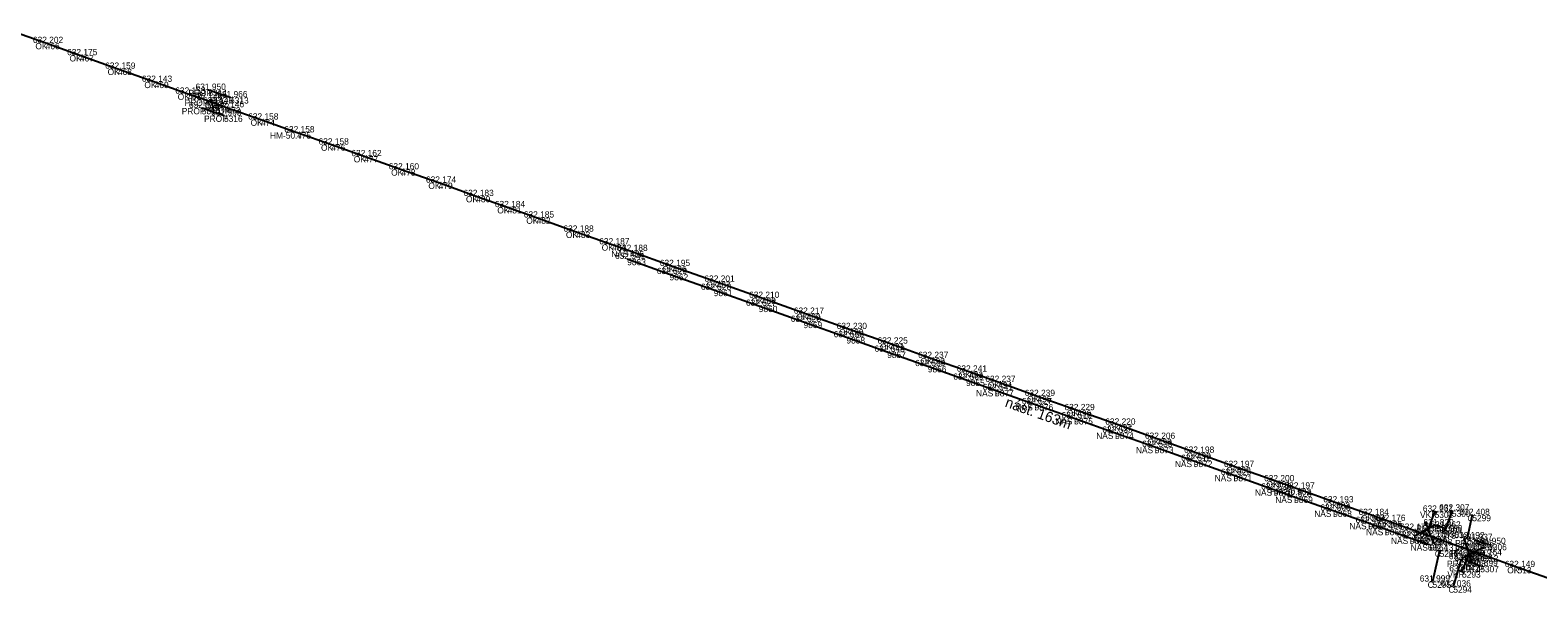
# Model space of a CAD drawing. Extents: x -631472 to -620808, y -1122356 to -1115125.
# Drawn here: x -628808.2 to -628519.1, y -1116376 to -1116268.1 of the extents above; entities that cross this region are included whole.
import ezdxf

# ---------------------------------------------------------------- set-up
doc = ezdxf.new("R2010")
doc.units = 0
for name, color, linetype in [('Vrstva 1', 7, 'Continuous'), ('Vrstva 14', 7, 'Continuous'), ('Vrstva 18', 7, 'Continuous'), ('Vrstva 4', 7, 'Continuous'), ('Vrstva 51', 7, 'Continuous'), ('Vrstva 60', 7, 'Continuous'), ('Vrstva 61', 7, 'Continuous'), ('Vrstva 62', 7, 'Continuous')]:
    doc.layers.add(name, color=color, linetype=linetype)

msp = doc.modelspace()

# ---------------------------------------------------------------- linework, layer by layer
at = {"layer": 'Vrstva 1'}
msp.add_lwpolyline([(-628812.06, -1116268.09), (-628805.17, -1116270.55), (-628798.61, -1116272.89), (-628791.32, -1116275.49), (-628784.27, -1116278), (-628777.88, -1116280.27), (-628774.68, -1116281.4), (-628772.66, -1116282.12), (-628770.48, -1116282.89), (-628763.9, -1116285.23), (-628756.97, -1116287.69), (-628750.4, -1116290.02), (-628744.11, -1116292.25), (-628736.94, -1116294.79), (-628729.81, -1116297.33), (-628722.61, -1116299.9), (-628716.6, -1116302.03), (-628711.03, -1116304.02), (-628703.43, -1116306.73), (-628696.58, -1116309.17), (-628693.1, -1116310.42), (-628684.96, -1116313.32), (-628676.51, -1116316.33), (-628667.85, -1116319.42), (-628659.27, -1116322.47), (-628651.05, -1116325.4), (-628643.21, -1116328.19), (-628635.44, -1116330.95), (-628628.12, -1116333.56), (-628622.55, -1116335.55), (-628614.99, -1116338.24), (-628607.38, -1116340.95), (-628599.55, -1116343.73), (-628591.93, -1116346.45), (-628584.44, -1116349.12), (-628576.8, -1116351.85), (-628569.1, -1116354.59), (-628565.19, -1116355.99), (-628557.75, -1116358.64), (-628550.97, -1116361.05), (-628547.78, -1116362.19), (-628543.02, -1116363.89), (-628539.28, -1116365.22), (-628538.12, -1116365.64), (-628532.43, -1116367.66), (-628531.94, -1116367.83), (-628530.62, -1116368.3), (-628529.3, -1116368.78), (-628522.94, -1116371.04), (-628516.08, -1116373.48)], dxfattribs=at)
at = {"layer": 'Vrstva 14'}
msp.add_lwpolyline([(-628693.66, -1116311.96), (-628685.54, -1116314.86), (-628677.07, -1116317.89), (-628668.44, -1116320.95), (-628659.85, -1116324.02), (-628651.63, -1116326.97), (-628643.8, -1116329.76), (-628636.01, -1116332.51), (-628628.69, -1116335.12), (-628623.13, -1116337.11), (-628615.55, -1116339.8), (-628607.94, -1116342.49), (-628600.1, -1116345.27), (-628592.48, -1116348), (-628585.02, -1116350.67), (-628577.38, -1116353.39), (-628569.66, -1116356.17), (-628565.77, -1116357.54), (-628558.29, -1116360.21), (-628551.55, -1116362.58), (-628548.35, -1116363.73), (-628543.57, -1116365.41), (-628539.81, -1116366.7)], dxfattribs=at)
at = {"layer": 'Vrstva 18'}
for p, q in [((-628773.98, -1116279.53), (-628769.82, -1116280.96)), ((-628775.25, -1116283.01), (-628770.98, -1116284.47)), ((-628538.54, -1116363.03), (-628537.2, -1116363.46)), ((-628531.09, -1116365.85), (-628528.58, -1116366.62)), ((-628532.63, -1116369.8), (-628530.09, -1116370.83))]:
    msp.add_line(p, q, dxfattribs=at)
at = {"layer": 'Vrstva 4'}
for p, q in [((-628538.38, -1116360.59), (-628539.32, -1116360.24)), ((-628538.74, -1116362.97), (-628542.77, -1116365.19)), ((-628539.03, -1116366.6), (-628540.61, -1116362.27)), ((-628538.85, -1116360.42), (-628540.08, -1116363.7)), ((-628538.12, -1116365.64), (-628532.43, -1116367.66)), ((-628533.17, -1116365.7), (-628531.76, -1116370.09)), ((-628533.6, -1116369.32), (-628529.48, -1116367.25)), ((-628533.59, -1116371.87), (-628532.23, -1116368.64)), ((-628534.05, -1116371.68), (-628533.13, -1116372.06))]:
    msp.add_line(p, q, dxfattribs=at)
at = {"layer": 'Vrstva 51'}
for p, q in [((-628535.53, -1116360.2), (-628536.86, -1116364.18)), ((-628531.62, -1116361.04), (-628532.62, -1116365.5)), ((-628537.89, -1116367.89), (-628539.25, -1116373.82)), ((-628535.26, -1116374.76), (-628533.68, -1116369.53))]:
    msp.add_line(p, q, dxfattribs=at)
at = {"layer": 'Vrstva 60'}
for p, q in [((-628805.17, -1116270.55), (-628805.17, -1116270.55)), ((-628798.61, -1116272.89), (-628798.61, -1116272.89)), ((-628791.32, -1116275.49), (-628791.32, -1116275.49)), ((-628784.27, -1116278), (-628784.27, -1116278)), ((-628777.88, -1116280.27), (-628777.88, -1116280.27)), ((-628774.68, -1116281.4), (-628774.68, -1116281.4)), ((-628772.66, -1116282.12), (-628772.66, -1116282.12)), ((-628770.48, -1116282.89), (-628770.48, -1116282.89)), ((-628763.9, -1116285.23), (-628763.9, -1116285.23)), ((-628756.97, -1116287.69), (-628756.97, -1116287.69)), ((-628750.4, -1116290.02), (-628750.4, -1116290.02)), ((-628744.11, -1116292.25), (-628744.11, -1116292.25)), ((-628736.94, -1116294.79), (-628736.94, -1116294.79)), ((-628729.81, -1116297.33), (-628729.81, -1116297.33)), ((-628722.61, -1116299.9), (-628722.61, -1116299.9)), ((-628716.6, -1116302.03), (-628716.6, -1116302.03)), ((-628711.03, -1116304.02), (-628711.03, -1116304.02)), ((-628703.43, -1116306.73), (-628703.43, -1116306.73)), ((-628696.58, -1116309.17), (-628696.58, -1116309.17)), ((-628693.1, -1116310.42), (-628693.1, -1116310.42)), ((-628693.66, -1116311.96), (-628693.66, -1116311.96)), ((-628684.96, -1116313.32), (-628684.96, -1116313.32)), ((-628685.54, -1116314.86), (-628685.54, -1116314.86)), ((-628676.51, -1116316.33), (-628676.51, -1116316.33)), ((-628677.07, -1116317.89), (-628677.07, -1116317.89)), ((-628667.85, -1116319.42), (-628667.85, -1116319.42)), ((-628668.44, -1116320.95), (-628668.44, -1116320.95)), ((-628659.27, -1116322.47), (-628659.27, -1116322.47)), ((-628659.85, -1116324.02), (-628659.85, -1116324.02)), ((-628651.05, -1116325.4), (-628651.05, -1116325.4)), ((-628651.63, -1116326.97), (-628651.63, -1116326.97)), ((-628643.21, -1116328.19), (-628643.21, -1116328.19)), ((-628643.8, -1116329.76), (-628643.8, -1116329.76)), ((-628635.44, -1116330.95), (-628635.44, -1116330.95)), ((-628636.01, -1116332.51), (-628636.01, -1116332.51)), ((-628628.12, -1116333.56), (-628628.12, -1116333.56)), ((-628628.69, -1116335.12), (-628628.69, -1116335.12)), ((-628623.13, -1116337.11), (-628623.13, -1116337.11)), ((-628622.55, -1116335.55), (-628622.55, -1116335.55)), ((-628615.55, -1116339.8), (-628615.55, -1116339.8)), ((-628614.99, -1116338.24), (-628614.99, -1116338.24)), ((-628607.94, -1116342.49), (-628607.94, -1116342.49)), ((-628607.38, -1116340.95), (-628607.38, -1116340.95)), ((-628600.1, -1116345.27), (-628600.1, -1116345.27)), ((-628599.55, -1116343.73), (-628599.55, -1116343.73)), ((-628592.48, -1116348), (-628592.48, -1116348)), ((-628591.93, -1116346.45), (-628591.93, -1116346.45)), ((-628585.02, -1116350.67), (-628585.02, -1116350.67)), ((-628584.44, -1116349.12), (-628584.44, -1116349.12)), ((-628577.38, -1116353.39), (-628577.38, -1116353.39)), ((-628576.8, -1116351.85), (-628576.8, -1116351.85)), ((-628569.1, -1116354.59), (-628569.1, -1116354.59)), ((-628569.66, -1116356.17), (-628569.66, -1116356.17)), ((-628565.19, -1116355.99), (-628565.19, -1116355.99)), ((-628565.77, -1116357.54), (-628565.77, -1116357.54)), ((-628558.29, -1116360.21), (-628558.29, -1116360.21)), ((-628557.75, -1116358.64), (-628557.75, -1116358.64)), ((-628551.55, -1116362.58), (-628551.55, -1116362.58)), ((-628550.97, -1116361.05), (-628550.97, -1116361.05)), ((-628547.78, -1116362.19), (-628547.78, -1116362.19)), ((-628548.35, -1116363.73), (-628548.35, -1116363.73)), ((-628543.57, -1116365.41), (-628543.57, -1116365.41)), ((-628543.02, -1116363.89), (-628543.02, -1116363.89)), ((-628539.28, -1116365.22), (-628539.28, -1116365.22)), ((-628538.12, -1116365.64), (-628538.12, -1116365.64)), ((-628539.81, -1116366.7), (-628539.81, -1116366.7)), ((-628532.43, -1116367.66), (-628532.43, -1116367.66)), ((-628531.94, -1116367.83), (-628531.94, -1116367.83)), ((-628530.62, -1116368.3), (-628530.62, -1116368.3)), ((-628529.3, -1116368.78), (-628529.3, -1116368.78)), ((-628522.94, -1116371.04), (-628522.94, -1116371.04))]:
    msp.add_line(p, q, dxfattribs=at)

# ---------------------------------------------------------------- texts
at = {"layer": 'Vrstva 14'}
msp.add_text('nást. 163m', height=2, rotation=340.421, dxfattribs=at).set_placement((-628621.37, -1116340.24))
at = {"layer": 'Vrstva 60'}
for s, p in [('466', (-628805.17, -1116271.75)), ('467', (-628798.61, -1116274.09)), ('468', (-628791.32, -1116276.69)), ('469', (-628784.27, -1116279.2)), ('470', (-628777.88, -1116281.47)), ('471', (-628774.68, -1116282.6)), ('5314', (-628773.98, -1116280.73)), ('472', (-628772.66, -1116283.32)), ('5313', (-628769.82, -1116282.16)), ('5315', (-628775.25, -1116284.21)), ('5316', (-628770.98, -1116285.67)), ('473', (-628770.48, -1116284.09)), ('474', (-628763.9, -1116286.43)), ('475', (-628756.97, -1116288.89)), ('476', (-628750.4, -1116291.22)), ('477', (-628744.11, -1116293.45)), ('478', (-628736.94, -1116295.99)), ('479', (-628729.81, -1116298.53)), ('480', (-628722.61, -1116301.1)), ('481', (-628716.6, -1116303.23)), ('482', (-628711.03, -1116305.22)), ('483', (-628703.43, -1116307.93)), ('484', (-628696.58, -1116310.37)), ('485', (-628693.1, -1116311.61)), ('9863', (-628693.66, -1116313.16)), ('486', (-628684.96, -1116314.52)), ('9862', (-628685.54, -1116316.06)), ('487', (-628676.51, -1116317.53)), ('9861', (-628677.07, -1116319.09)), ('488', (-628667.85, -1116320.61)), ('9860', (-628668.44, -1116322.15)), ('489', (-628659.27, -1116323.67)), ('9859', (-628659.85, -1116325.22)), ('490', (-628651.05, -1116326.6)), ('9858', (-628651.63, -1116328.17)), ('491', (-628643.21, -1116329.39)), ('9857', (-628643.8, -1116330.96)), ('492', (-628635.44, -1116332.15)), ('9856', (-628636.01, -1116333.71)), ('493', (-628628.12, -1116334.76)), ('9855', (-628628.69, -1116336.32)), ('9877', (-628623.13, -1116338.31)), ('494', (-628622.55, -1116336.75)), ('9876', (-628615.55, -1116341)), ('495', (-628614.99, -1116339.44)), ('9875', (-628607.94, -1116343.69)), ('496', (-628607.38, -1116342.15)), ('9874', (-628600.1, -1116346.47)), ('497', (-628599.55, -1116344.93)), ('9873', (-628592.48, -1116349.2)), ('498', (-628591.93, -1116347.65)), ('9872', (-628585.02, -1116351.87)), ('499', (-628584.44, -1116350.32)), ('9871', (-628577.38, -1116354.59)), ('500', (-628576.8, -1116353.05)), ('501', (-628569.1, -1116355.79)), ('9870', (-628569.66, -1116357.36)), ('502', (-628565.19, -1116357.19)), ('9869', (-628565.77, -1116358.74)), ('9868', (-628558.29, -1116361.41)), ('503', (-628557.75, -1116359.84)), ('5300', (-628535.53, -1116361.4)), ('9867', (-628551.55, -1116363.78)), ('504', (-628550.97, -1116362.26)), ('505', (-628547.78, -1116363.39)), ('5302', (-628538.85, -1116361.62)), ('5303', (-628538.54, -1116364.23)), ('5299', (-628531.62, -1116362.24)), ('9866', (-628548.35, -1116364.93)), ('9865', (-628543.57, -1116366.61)), ('506', (-628543.02, -1116365.09)), ('507', (-628539.28, -1116366.42)), ('508', (-628538.12, -1116366.84)), ('5304', (-628537.2, -1116364.66)), ('5301', (-628536.86, -1116365.38)), ('5298', (-628532.62, -1116366.7)), ('5305', (-628531.09, -1116367.05)), ('9864', (-628539.81, -1116367.9)), ('5296', (-628537.89, -1116369.09)), ('509', (-628532.43, -1116368.86)), ('510', (-628531.94, -1116369.03)), ('511', (-628530.62, -1116369.5)), ('512', (-628529.3, -1116369.98)), ('5306', (-628528.58, -1116367.82)), ('5297', (-628533.68, -1116370.73)), ('5293', (-628533.59, -1116373.07)), ('5308', (-628532.63, -1116371)), ('5307', (-628530.09, -1116372.03)), ('513', (-628522.94, -1116372.24)), ('5295', (-628539.25, -1116375.02)), ('5294', (-628535.26, -1116375.96))]:
    msp.add_text(s, height=1.2, dxfattribs=at).set_placement(p)
at = {"layer": 'Vrstva 61'}
for s, p in [('632.202', (-628807.62, -1116270.55)), ('632.175', (-628801.07, -1116272.89)), ('632.159', (-628793.77, -1116275.49)), ('632.143', (-628786.72, -1116278)), ('632.153', (-628780.33, -1116280.27)), ('631.950', (-628776.43, -1116279.53)), ('632.038', (-628777.7, -1116283.01)), ('632.146', (-628777.13, -1116281.4)), ('632.141', (-628775.02, -1116282.12)), ('632.146', (-628772.93, -1116282.89)), ('631.966', (-628772.27, -1116280.96)), ('631.993', (-628773.43, -1116284.47)), ('632.158', (-628766.35, -1116285.23)), ('632.158', (-628759.42, -1116287.69)), ('632.158', (-628752.85, -1116290.02)), ('632.162', (-628746.56, -1116292.25)), ('632.160', (-628739.39, -1116294.79)), ('632.174', (-628732.26, -1116297.33)), ('632.183', (-628725.06, -1116299.9)), ('632.184', (-628719.05, -1116302.03)), ('632.185', (-628713.49, -1116304.02)), ('632.188', (-628705.89, -1116306.73)), ('632.187', (-628699.03, -1116309.17)), ('632.541', (-628696.01, -1116311.96)), ('632.188', (-628695.55, -1116310.42)), ('632.529', (-628687.99, -1116314.86)), ('632.195', (-628687.41, -1116313.32)), ('632.528', (-628679.53, -1116317.89)), ('632.201', (-628678.86, -1116316.33)), ('632.527', (-628670.89, -1116320.95)), ('632.210', (-628670.3, -1116319.42)), ('632.528', (-628662.3, -1116324.02)), ('632.217', (-628661.72, -1116322.47)), ('632.230', (-628653.5, -1116325.4)), ('632.558', (-628654.08, -1116326.97)), ('632.548', (-628646.25, -1116329.76)), ('632.225', (-628645.66, -1116328.19)), ('632.559', (-628638.47, -1116332.51)), ('632.237', (-628637.89, -1116330.95)), ('632.569', (-628631.14, -1116335.12)), ('632.241', (-628630.48, -1116333.56)), ('632.237', (-628625, -1116335.55)), ('632.541', (-628625.49, -1116337.11)), ('632.239', (-628617.44, -1116338.24)), ('632.527', (-628618, -1116339.8)), ('632.229', (-628609.83, -1116340.95)), ('632.518', (-628610.39, -1116342.49)), ('632.220', (-628602, -1116343.73)), ('632.535', (-628602.56, -1116345.27)), ('632.206', (-628594.39, -1116346.45)), ('632.533', (-628594.93, -1116348)), ('632.198', (-628586.9, -1116349.12)), ('632.512', (-628587.46, -1116350.67)), ('632.197', (-628579.25, -1116351.85)), ('632.525', (-628579.84, -1116353.39)), ('632.200', (-628571.55, -1116354.59)), ('632.530', (-628572.11, -1116356.17)), ('632.528', (-628568.22, -1116357.54)), ('632.197', (-628567.64, -1116355.99)), ('632.193', (-628560.2, -1116358.64)), ('632.508', (-628560.75, -1116360.21)), ('632.184', (-628553.43, -1116361.05)), ('632.251', (-628541.1, -1116360.42)), ('632.307', (-628537.98, -1116360.2)), ('632.408', (-628534.07, -1116361.04)), ('632.496', (-628554, -1116362.58)), ('632.486', (-628550.8, -1116363.73)), ('632.176', (-628550.23, -1116362.19)), ('632.173', (-628545.47, -1116363.89)), ('631.820', (-628540.99, -1116363.03)), ('631.862', (-628539.65, -1116363.46)), ('632.190', (-628539.31, -1116364.18)), ('632.018', (-628546.03, -1116365.41)), ('632.090', (-628542.26, -1116366.7)), ('632.174', (-628541.73, -1116365.22)), ('632.176', (-628540.57, -1116365.64)), ('632.192', (-628535.07, -1116365.5)), ('631.937', (-628533.54, -1116365.85)), ('631.950', (-628531.03, -1116366.62)), ('632.131', (-628540.14, -1116367.89)), ('632.182', (-628536.13, -1116369.53)), ('631.895', (-628535.09, -1116369.8)), ('632.177', (-628534.88, -1116367.66)), ('632.176', (-628534.39, -1116367.83)), ('632.170', (-628533.07, -1116368.3)), ('632.164', (-628531.75, -1116368.78)), ('632.042', (-628536.04, -1116371.87)), ('631.899', (-628532.54, -1116370.83)), ('632.149', (-628525.39, -1116371.04)), ('631.999', (-628541.7, -1116373.82)), ('632.036', (-628537.71, -1116374.76))]:
    msp.add_text(s, height=1.2, dxfattribs=at).set_placement(p)
at = {"layer": 'Vrstva 62'}
for s, p in [('OK', (-628807.15, -1116271.75)), ('OK', (-628800.6, -1116274.09)), ('OK', (-628793.3, -1116276.69)), ('OK', (-628786.25, -1116279.2)), ('OK', (-628779.86, -1116281.47)), ('PROP', (-628778.52, -1116282.6)), ('PROP', (-628777.81, -1116280.73)), ('OK', (-628774.65, -1116283.32)), ('PROP', (-628773.65, -1116282.16)), ('PROP', (-628779.08, -1116284.21)), ('PROP', (-628774.81, -1116285.67)), ('PROP', (-628774.31, -1116284.09)), ('OK', (-628765.88, -1116286.43)), ('HM-50.7', (-628762.17, -1116288.89)), ('OK', (-628752.38, -1116291.22)), ('OK', (-628746.1, -1116293.45)), ('OK', (-628738.93, -1116295.99)), ('OK', (-628731.8, -1116298.53)), ('OK', (-628724.59, -1116301.1)), ('OK', (-628718.58, -1116303.23)), ('OK', (-628713.02, -1116305.22)), ('OK', (-628705.42, -1116307.93)), ('OK', (-628698.56, -1116310.37)), ('NAST', (-628696.74, -1116311.61)), ('OK', (-628686.94, -1116314.52)), ('OK', (-628678.49, -1116317.53)), ('OK', (-628669.84, -1116320.61)), ('OK', (-628661.25, -1116323.67)), ('OK', (-628653.03, -1116326.6)), ('OK', (-628645.19, -1116329.39)), ('OK', (-628637.42, -1116332.15)), ('OK', (-628630.11, -1116334.76)), ('NAST', (-628626.77, -1116338.31)), ('OK', (-628624.53, -1116336.75)), ('NAST', (-628619.19, -1116341)), ('OK', (-628616.97, -1116339.44)), ('NAST', (-628611.58, -1116343.69)), ('OK', (-628609.36, -1116342.15)), ('NAST', (-628603.74, -1116346.47)), ('OK', (-628601.54, -1116344.93)), ('NAST', (-628596.12, -1116349.2)), ('OK', (-628593.92, -1116347.65)), ('NAST', (-628588.66, -1116351.87)), ('OK', (-628586.43, -1116350.32)), ('NAST', (-628581.02, -1116354.59)), ('OK', (-628578.78, -1116353.05)), ('OK', (-628571.08, -1116355.79)), ('NAST', (-628573.3, -1116357.36)), ('HM-50.9', (-628570.4, -1116357.19)), ('NAST', (-628569.41, -1116358.74)), ('NAST', (-628561.93, -1116361.41)), ('OK', (-628559.73, -1116359.84)), ('C', (-628536.47, -1116361.4)), ('NAST', (-628555.19, -1116363.78)), ('OK', (-628552.96, -1116362.26)), ('OK', (-628549.77, -1116363.39)), ('PROP', (-628542.38, -1116364.23)), ('VKR', (-628541.65, -1116361.62)), ('C', (-628532.56, -1116362.24)), ('NAST', (-628551.99, -1116364.93)), ('NAST', (-628547.21, -1116366.61)), ('OK', (-628545.01, -1116365.09)), ('NAST', (-628542.92, -1116366.42)), ('PROP', (-628541.03, -1116364.66)), ('PRJ', (-628540.61, -1116366.84)), ('C', (-628537.8, -1116365.38)), ('PROP', (-628534.92, -1116367.05)), ('C', (-628533.56, -1116366.7)), ('NAST', (-628543.45, -1116367.9)), ('C', (-628538.82, -1116369.09)), ('PROP', (-628535.77, -1116369.03)), ('PRJ', (-628534.92, -1116368.86)), ('PROP', (-628533.13, -1116369.98)), ('OK', (-628532.61, -1116369.5)), ('PROP', (-628532.41, -1116367.82)), ('VKR', (-628536.4, -1116373.07)), ('PROP', (-628536.47, -1116371)), ('C', (-628534.61, -1116370.73)), ('PROP', (-628533.92, -1116372.03)), ('OK', (-628524.92, -1116372.24)), ('C', (-628540.19, -1116375.02)), ('C', (-628536.2, -1116375.96))]:
    msp.add_text(s, height=1.2, dxfattribs=at).set_placement(p)

doc.saveas('drawing.dxf')
